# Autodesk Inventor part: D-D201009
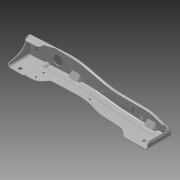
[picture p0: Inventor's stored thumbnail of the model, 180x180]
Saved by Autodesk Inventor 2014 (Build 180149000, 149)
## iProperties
Created: 2007-10
Part Number: D-D201009
Document SubType Name: Modeling
Designer: MM
Density: 7.85 g/cm^3
Mass: 1039.33 g
Surface Area: 1235.3 cm^2
Volume: 132.398 cm^3
Material: Steel
Description: TOP FRAME RIGHT SIDE PLATE
Appearance: Steel
Component Category: Lower Component
Author: MM
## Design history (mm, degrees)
sketch "Sketch2"
  geometry: L1 (-10, 0)-(-202.66, 0); L2 (-453.629, -13.843)-(-362.619, -13.843); L3 (-357.385, -13.706)-(-296.395, -10.51); L4 (-293.614, -10.266)-(-217.285, -0.894); L5 (-462.692, -8.069)-(-464.267, -4.692); L6 (-462.96, 10.251)-(-460.669, 13.523); L7 (-455.791, 17.222)-(-418.085, 30.463); L8 (-384.952, 36.111)-(-306.589, 36.111); L9 (-248.228, 43.019)-(-193.772, 56.092); L10 (-135.411, 63)-(-10, 63); L11 (0, 10)-(0, 53); A1 r 10 centre (-452.477, 7.787) between (-455.791, 17.222) and (-460.669, 13.523); A2 r 15 centre (-450.673, 1.647) between (-462.96, 10.251) and (-464.267, -4.692); A3 r 10 centre (-453.629, -3.843) between (-462.692, -8.069) and (-453.629, -13.843); A4 r 40 centre (-298.488, 29.435) between (-296.395, -10.51) and (-293.614, -10.266); A5 r 120 centre (-202.66, -120) between (-202.66, 0) and (-217.285, -0.894); A6 r 250 centre (-306.589, 286.111) between (-306.589, 36.111) and (-248.228, 43.019); A7 r 250 centre (-135.411, -187) between (-135.411, 63) and (-193.772, 56.092); A8 r 10 centre (-10, 53) between (0, 53) and (-10, 63); A9 r 10 centre (-10, 10) between (-10, 0) and (0, 10); A10 r 100 centre (-384.952, -63.889) between (-384.952, 36.111) and (-418.085, 30.463); A11 r 100 centre (-362.619, 86.157) between (-362.619, -13.843) and (-357.385, -13.706); 11 further points
  constraints: 22 end point, 22 point on circle, 22 point on line, 22 tangent, 11 centre point, 5 equal radius, 3 parallel, 1 horizontal, 1 perpendicular
  dimensions: "d0" = 210 distance of point (0, 0) point (-210, 0); "d1" = 85 horizontal distance of point (-210, 0) point (-295, -10.437); "d2" = 7 deg angle of L4 L1; "d3" = 65 horizontal distance of point (-360, -13.843) point (-295, -10.437); "d4" = 4 deg angle of L4 L3; "d5" = 460 horizontal distance of point (0, 0) point (-460, -13.843); "d6" = 65 deg angle of L5 L2; "d7" = 120 deg angle of L5 L6; "d8" = 17 vertical distance of point (-460, -13.843) point (-467.927, 3.157); "d9" = 30 vertical distance of point (-460, -13.843) point (-458.825, 16.157); "d10" = 63 distance of point (0, 0) point (0, 63); "d11" = 165 distance of point (-165, 63) point (0, 63); "d12" = 112 horizontal distance of point (-165, 63) point (-277, 36.111); "d13" = 13.5 deg angle of L10 L9; "d14" = 125 distance of point (-402, 36.111) point (-277, 36.111); "d15" = 10 radius of A1; "d16" = 15 radius of A2; "d17" = 40 radius of A4; "d18" = 120 radius of A5; "d19" = 250 radius of A6; "d26" = 100 radius of A10
extrude "Extrusion1" new body sketch "Sketch2" distance "d20" = 80; taper "d21" = 0 deg
sketch "Sketch3"
  geometry: L1 (0, 0)-(125.411, 0) reference; L2 (-10, 0)-(-10, -80) reference; L3 (125.411, 0)-(-10, -8.282); L4 (125.411, 0)-(-10, 0); L5 (-10, 0)-(-10, -8.282)
  constraints: 6 end point, 1 collinear, 1 perpendicular, 1 point on line
  dimensions: "d22" = 3.5 deg angle of L1 L3
extrude "Extrusion2" cut sketch "Sketch3" stored distance "d23" = 80; taper "d24" = 0 deg
fillet "Fillet1" dims "d25" = 500
sketch "Sketch4"
  geometry: L1 (202.66, 0)-(10, 0) reference; C1 r 8.5 at (60, -4.5); 1 further point
  constraints: 1 centre point
  dimensions: "d27" = 4.5 distance from line of C1.centre L1; "d28" = 60 horizontal distance of point (0, 0) C1.centre; "d29" = 17 diameter of C1
extrude "Extrusion3" cut sketch "Sketch4" stored distance "d30" = 80; taper "d31" = 0 deg
sketch "Sketch5"
  geometry: L1 (202.66, 0)-(67.211, 0) reference; L2 (293.614, -10.266)-(217.285, -0.894) reference; L3 (357.385, -13.706)-(296.395, -10.51) reference; L4 (453.629, -13.843)-(362.619, -13.843) reference; L5 (52.789, 0)-(10, 0) reference; L6 (60, -4.5)-(60, 4); L7 (202.66, 4)-(60, 4); L8 (461.629, -9.843)-(362.619, -9.843); L9 (357.594, -9.712)-(296.604, -6.515); L10 (294.101, -6.296)-(217.772, 3.076); A1 r 8.5 centre (60, -4.5) between (67.211, 0) and (52.789, 0) reference; A2 r 120 centre (202.66, -120) between (217.285, -0.894) and (202.66, 0) reference; A3 r 40 centre (298.488, 29.435) between (293.614, -10.266) and (296.395, -10.51) reference; A4 r 100 centre (362.619, 86.157) between (357.385, -13.706) and (362.619, -13.843) reference; A5 r 10 centre (453.629, -3.843) between (453.629, -13.843) and (462.692, -8.069) reference; A6 r 124 centre (202.66, -120) between (217.772, 3.076) and (202.66, 4); A7 r 96 centre (362.619, 86.157) between (357.594, -9.712) and (362.619, -9.843); A8 r 36 centre (298.488, 29.435) between (294.101, -6.296) and (296.604, -6.515); 1 further point
  constraints: 10 end point, 8 point on circle, 3 centre point, 2 parallel, 1 perpendicular, 1 tangent, 3 other
  dimensions: "d32" = 4 distance between parallel lines of L4 L8
extrude "Extrusion4" cut sketch "Sketch5" distance "d33" = 55; taper "d34" = 0 deg
fillet "Fillet4" dims "d38" = 10
fillet "Fillet5" dims "d39" = 10
fillet "Fillet6" dims "d40" = 3
fillet "Fillet7" dims "d41" = 3
workplane "Work Plane1"
sketch "Sketch10"
  geometry: L1 (-10, 58)-(-10, 80) reference; L2 (-10, 80)-(52.574, 80) reference; L3 (52.574, 80)-(52.574, 0) reference; L4 (52.574, 0)-(-6, 0) reference; L5 (-6, 0)-(-6, 52.343) reference; L6 (-10, 68)-(15.981, 83); L7 (15.981, 83)-(-10, 83); L8 (-10, 83)-(-10, 68); A1 r 3 centre (-9, 52.343) between (-6, 52.343) and (-8, 55.172) reference; A2 r 3 centre (-7, 58) between (-10, 58) and (-8, 55.172) reference; 1 further point
  constraints: 6 end point, 2 point on line, 1 collinear, 1 perpendicular
  dimensions: "d89" = 12 distance of L6.start point (-10, 80); "d90" = 60 deg angle of L1 L6; "d91" = 15 distance of L7.end L6.start
extrude "Extrusion9" cut sketch "Sketch10" stored distance "d92" = 40; taper "d93" = 0 deg
chamfer "Chamfer2" distance "d97" = 8; stored, may be unused: second distance "d98" = 20.48336, angle "d99" = 60 deg
chamfer "Chamfer3" distance "d100" = 8; stored, may be unused: second distance "d101" = 20.48336, angle "d102" = 60 deg
fillet "Fillet13" dims "d103" = 5
fillet "Fillet14" dims "d104" = 5
workplane "Work Plane2"
sketch "Sketch11"
  geometry: L1 (-23.843, 58)-(-23.843, 80) reference; L2 (-23.843, 80)-(24.973, 80) reference; L3 (24.973, 0)-(-19.843, 0) reference; L4 (-19.843, 0)-(-19.843, 52.343) reference; L5 (-23.843, 68)-(2.138, 83); L6 (2.138, 83)-(-23.843, 83); L7 (-23.843, 83)-(-23.843, 68); L8 (24.973, 80)-(24.973, 0) reference; A1 r 3 centre (-22.843, 52.343) between (-19.843, 52.343) and (-21.843, 55.172) reference; A2 r 3 centre (-20.843, 58) between (-23.843, 58) and (-21.843, 55.172) reference; 1 further point
  constraints: 6 end point, 1 collinear, 1 perpendicular, 1 point on line
  dimensions: "d106" = 12 distance of L5.start L1.end; "d107" = 60 deg angle of L5 L1; "d108" = 15 distance from line of L6 L5.start
extrude "Extrusion10" cut sketch "Sketch11" stored distance "d109" = 40; taper "d110" = 0 deg
chamfer "Chamfer4" distance "d111" = 8; stored, may be unused: second distance "d112" = 20.48336, angle "d113" = 60 deg
fillet "Fillet15" dims "d114" = 5
fillet "Fillet16" dims "d115" = 5
fillet "Fillet8" dims "d42" = 5
shell "Shell1" dims "d43" = 2.2
sketch "Sketch6"
  geometry: L1 (0, 0)-(43, 0) reference; L2 (43, 67.014)-(43, 0) reference; L3 (44.783, 61.182)-(35.908, 59.229); L4 (53, 67.32)-(53, 0) reference; L5 (52.306, 62)-(53, 62); L6 (16.726, 46.966)-(14.888, 44.549); L7 (6.448, 27.408)-(0.604, 5.902); L8 (-7.116, 0)-(-9, 0); L9 (-9, 0)-(-9, -7); L10 (-9, -7)-(53, -7); L11 (53, 62)-(53, -7); A1 r 33 centre (43, 27) between (35.908, 59.229) and (16.726, 46.966); A2 r 50 centre (54.698, 14.297) between (14.888, 44.549) and (6.448, 27.408); A3 r 35 centre (52.306, 27) between (52.306, 62) and (44.783, 61.182); A4 r 8 centre (-7.116, 8) between (-7.116, 0) and (0.604, 5.902); 4 further points
  constraints: 16 end point, 8 point on circle, 8 point on line, 8 tangent, 4 centre point, 3 perpendicular, 2 parallel, 1 collinear
  dimensions: "d44" = 62 distance from line of L4.end L5; "d45" = 66 diameter of A1; "d46" = 27 distance of A1.centre L1.end; "d47" = 4.5 distance of point (48.5, 62) L5.end; "d48" = 36.8 distance from line of L1 point (9, 36.8); "d49" = 54 distance from line of L4 point (-1, 0); "d50" = 62 distance between parallel lines of L11 L9; "d51" = 7 distance from line of L1.end L10; "d52" = 44 distance from line of L4 point (9, 36.8); "d53" = 50 radius of A2; "d54" = 35 radius of A3; "d55" = 8 radius of A4
extrude "Extrusion5" cut sketch "Sketch6" distance "d56" = 6; taper "d57" = 0 deg
sketch "Sketch7"
  geometry: L1 (0, 67.32)-(110.468, 74.077) reference; L2 (0, 67.32)-(0, 0) reference; L3 (0, 0)-(125.411, 0) reference; L4 (-4, 62)-(-4, 0) reference; L5 (-4, 62)-(-3.713, 62); L6 (2.283, 55.79)-(2.109, 50.802); L7 (10.592, 42.537)-(42.459, 44.486); L8 (49.966, 52.192)-(50.136, 57.07); L9 (54.134, 60.93)-(56.063, 60.93); L10 (57.435, 61.173)-(81.606, 70); L11 (43.814, 70)-(435, 70); L12 (237.061, 80)-(182.605, 80) reference; L13 (435, 70)-(435, 0); L14 (435, 0)-(-4, 0); L15 (-4, 0)-(-4, 62); A1 r 6 centre (-3.713, 56) between (2.283, 55.79) and (-3.713, 62); A2 r 8 centre (10.104, 50.522) between (2.109, 50.802) and (10.592, 42.537); A3 r 8 centre (41.971, 52.472) between (42.459, 44.486) and (49.966, 52.192); A4 r 4 centre (54.134, 56.93) between (54.134, 60.93) and (50.136, 57.07); A5 r 4 centre (56.063, 64.93) between (56.063, 60.93) and (57.435, 61.173); 8 further points
  constraints: 20 end point, 15 point on line, 10 point on circle, 10 tangent, 5 centre point, 4 parallel, 2 collinear, 2 equal radius, 2 perpendicular
  dimensions: "d58" = 10 distance between parallel lines of L11 L12; "d59" = 6.5 distance of L4.start point (2.5, 62); "d60" = 20 vertical distance of point (2.5, 62) point (1.802, 42); "d61" = 88 deg angle of L5 L6; "d62" = 48 distance of point (1.802, 42) point (49.712, 44.93); "d63" = 16 vertical distance of point (49.712, 44.93) point (50.271, 60.93); "d64" = 6.5 distance of point (50.271, 60.93) point (56.771, 60.93); "d65" = 31 distance from line of L10.end L8; "d66" = 435 distance between parallel lines of L2 L13; "d67" = 6 radius of A1; "d68" = 8 radius of A2; "d69" = 4 radius of A4
extrude "Extrusion6" cut sketch "Sketch7" distance "d72" = 45; taper "d73" = 0 deg
sketch "Sketch9"
  geometry: L1 (445, 21.011)-(445, 18.68) reference; L2 (445, 18.68)-(455.062, 15.146) reference; L3 (458.867, 12.261)-(461.158, 8.989) reference; L4 (445, 21.011)-(455.791, 17.222) reference; L5 (460.669, 13.523)-(458.867, 12.261); A1 r 7.8 centre (452.477, 7.787) between (458.867, 12.261) and (455.062, 15.146) reference; A2 r 10 centre (452.477, 7.787) between (460.669, 13.523) and (455.791, 17.222) reference; 1 further point
  constraints: 2 end point, 1 perpendicular
extrude "Extrusion7" cut sketch "Sketch9" distance "d75" = 73; taper "d76" = 0 deg
sketch "Sketch8"
  geometry: L1 (156.108, -22.121)-(101.652, -9.047) reference; L2 (293.346, -29.089)-(214.983, -29.089) reference; L3 (353.394, -44.32)-(325.749, -34.613) reference; L4 (43.804, -8.2)-(5, -8.2); L5 (351.406, -49.981)-(323.761, -40.274); L6 (293.346, -35.089)-(214.983, -35.089); L7 (154.707, -27.955)-(100.251, -14.881); L8 (353.394, -44.32)-(351.406, -49.981); L9 (43.804, -2.2)-(0, -2.2) reference; L10 (5, -8.2)-(5, -2.2); L11 (0, 0)-(0, -2.2) reference; A1 r 247.8 centre (43.804, -250) between (101.652, -9.047) and (43.804, -2.2) reference; A2 r 252.2 centre (214.983, 223.111) between (156.108, -22.121) and (214.983, -29.089) reference; A3 r 97.8 centre (293.346, -126.889) between (325.749, -34.613) and (293.346, -29.089) reference; A4 r 91.8 centre (293.346, -126.889) between (323.761, -40.274) and (293.346, -35.089); A5 r 258.2 centre (214.983, 223.111) between (154.707, -27.955) and (214.983, -35.089); A6 r 241.8 centre (43.804, -250) between (100.251, -14.881) and (43.804, -8.2); 1 further point
  constraints: 12 end point, 6 point on circle, 3 centre point, 2 perpendicular, 1 point on line, 4 other
  dimensions: "d77" = 6 distance between parallel lines of L3 L5; "d78" = 6 radial gap between concentric circles of A3 A4; "d81" = 5 distance between parallel lines of L11 L10; "d82" = 6 distance between parallel lines of L9 L4
extrude "Extrusion8" join sketch "Sketch8" distance "d79" = 2.2; taper "d80" = 0 deg
fillet "Fillet9" dims "d83" = 2.5
fillet "Fillet10" dims "d84" = 0.3
fillet "Fillet11" dims "d85" = 10
fillet "Fillet12" dims "d86" = 5
sketch "Sketch12"
  geometry: L1 (38.511, 67.32)-(38.511, 0) reference; L2 (0, 0)-(-28.281, 0); L3 (-47.011, 3.641)-(-48.511, 4.247); L4 (-63.601, 18.819)-(-63.95, 19.603); L5 (-74.494, 26.715)-(-168.594, 30.001); L6 (-205.015, 26.814)-(-216.579, 24.356); L7 (-247.766, 21.078)-(-298.348, 21.078); L8 (-328.989, 6.79)-(-349.791, -18); L9 (-349.791, -18)-(0, -18); L10 (0, -18)-(0, 0); L11 (-11.489, 0)-(-154.15, 0) reference; A1 r 10 centre (-186.122, 20.607) between (-185.773, 30.6) and (-188.201, 30.388); A2 r 50 centre (-28.281, 50) between (-47.011, 3.641) and (-28.281, 0); A3 r 28 centre (-38.022, 30.208) between (-63.601, 18.819) and (-48.511, 4.247); A4 r 12 centre (-74.913, 14.722) between (-63.95, 19.603) and (-74.494, 26.715); A5 r 150 centre (-173.828, -119.908) between (-168.594, 30.001) and (-205.015, 26.814); A6 r 150 centre (-247.766, 171.078) between (-247.766, 21.078) and (-216.579, 24.356); A7 r 40 centre (-298.348, -18.922) between (-298.348, 21.078) and (-328.989, 6.79); 7 further points
  constraints: 18 end point, 14 point on circle, 14 point on line, 14 tangent, 7 centre point, 2 parallel, 2 perpendicular, 1 equal radius
  dimensions: "d116" = 18 distance of L9.end L2.start; "d117" = 38 distance of L2.start point (-38, 0); "d118" = 21 horizontal distance of point (-59, 8.485) point (-38, 0); "d119" = 22 deg angle of L3 L2; "d120" = 8 horizontal distance of point (-59, 8.485) point (-67, 26.453); "d121" = 66 deg angle of L2 L4; "d122" = 120 horizontal distance of point (-187, 30.643) point (-67, 26.453); "d123" = 2 deg angle of L11 L5; "d124" = 45 horizontal distance of point (-232, 21.078) point (-187, 30.643); "d125" = 12 deg angle of L9 L6; "d126" = 85 distance of point (-232, 21.078) point (-317, 21.078); "d127" = 50 deg angle of L8 L7; "d128" = 10 radius of A1; "d129" = 50 radius of A2; "d130" = 28 radius of A3; "d131" = 12 radius of A4; "d132" = 150 radius of A5; "d133" = 40 radius of A7
extrude "Extrusion11" cut sketch "Sketch12" stored distance "d134" = 40; taper "d135" = 0 deg
fillet "Fillet17" dims "d136" = 20
fillet "Fillet18" dims "d137" = 10
sketch "Sketch13"
  geometry: L1 (384.952, -31.111)-(306.589, -31.111) reference; L2 (296.657, 5.517)-(357.647, 8.713) reference; L3 (217.894, -4.068)-(294.223, 5.304) reference; L4 (334.231, -21.656)-(311.461, -21.656); L5 (332.236, -2.132)-(297.659, -3.944); L6 (294.878, -4.187)-(266.95, -7.616); L7 (339.15, -15.762)-(337.417, -6.231); L8 (262.873, -10.836)-(260.164, -18.12); A1 r 255 centre (306.589, -286.111) between (306.589, -31.111) and (247.061, -38.157) reference; A2 r 264.5 centre (306.589, -286.111) between (311.461, -21.656) and (265.625, -24.803); A3 r 40 centre (299.753, -43.889) between (297.659, -3.944) and (294.878, -4.187); A4 r 5 centre (264.851, -19.863) between (260.164, -18.12) and (265.625, -24.803); A5 r 5 centre (267.56, -12.579) between (266.95, -7.616) and (262.873, -10.836); A6 r 5 centre (334.231, -16.656) between (334.231, -21.656) and (339.15, -15.762); A7 r 5 centre (332.498, -7.125) between (337.417, -6.231) and (332.236, -2.132); 7 further points
  constraints: 12 point on circle, 10 end point, 10 tangent, 6 centre point, 6 point on line, 3 equal radius, 1 parallel
  dimensions: "d138" = 9.5 distance between parallel lines of L2 L5; "d139" = 9.5 distance between parallel lines of L3 L6; "d140" = 9.5 radial gap between concentric circles of A1 A2; "d142" = 40 radius of A3; "d144" = 19.7546 vertical distance of point (340.222, -21.656) point (336.63, -1.901); "d145" = 72.69753 horizontal distance of point (263.933, -7.987) point (336.63, -1.901); "d147" = 62.5985 deg angle of L8 L6; "d148" = 5 radius of A4; "d149" = 97.3028 deg angle of L5 L7; "d193" = 42.04198 distance from line of L7 point (377.408, 8.843)
extrude "Extrusion12" cut sketch "Sketch13" distance "d150" = 2.2; taper "d151" = 0 deg
sketch "Sketch14"
  geometry: L1 (32.561, -15.349)-(30.828, -24.881) reference; L2 (25.647, -28.979)-(-8.93, -27.167) reference; L3 (-11.711, -26.924)-(-39.639, -23.495) reference; L4 (-43.716, -20.275)-(-46.425, -12.991) reference; L5 (4.872, -9.455)-(27.641, -9.455) reference; L6 (-48.487, -13.758)-(-45.778, -21.042); L7 (-39.907, -25.679)-(-11.979, -29.108); L8 (-9.045, -29.364)-(25.532, -31.176); L9 (32.993, -25.274)-(34.725, -15.743); L10 (27.641, -7.255)-(4.851, -7.255); A1 r 5 centre (27.641, -14.455) between (32.561, -15.349) and (27.641, -9.455) reference; A2 r 5 centre (25.909, -23.986) between (25.647, -28.979) and (30.828, -24.881) reference; A3 r 40 centre (-6.837, 12.778) between (-11.711, -26.924) and (-8.93, -27.167) reference; A4 r 5 centre (-39.03, -18.532) between (-43.716, -20.275) and (-39.639, -23.495) reference; A5 r 5 centre (-41.739, -11.248) between (-40.965, -6.309) and (-46.425, -12.991) reference; A6 r 264.5 centre (0, 255) between (-40.965, -6.309) and (4.872, -9.455) reference; A7 r 7.2 centre (-39.03, -18.532) between (-45.778, -21.042) and (-39.907, -25.679); A8 r 42.2 centre (-6.837, 12.778) between (-11.979, -29.108) and (-9.045, -29.364); A9 r 7.2 centre (25.909, -23.986) between (25.532, -31.176) and (32.993, -25.274); A10 r 7.2 centre (27.641, -14.455) between (34.725, -15.743) and (27.641, -7.255); A11 r 262.3 centre (0, 255) between (-40.624, -4.135) and (4.851, -7.255); A12 r 7.2 centre (-41.739, -11.248) between (-40.624, -4.135) and (-48.487, -13.758); 1 further point
  constraints: 12 point on circle, 10 end point, 6 centre point, 10 other
  dimensions: "d152" = 2.2 radial gap between concentric circles of A6 A11
extrude "Extrusion13" join sketch "Sketch14" distance "d153" = 2.2; taper "d154" = 0 deg
fillet "Fillet19" dims "d155" = 2.2
fillet "Fillet20" dims "d156" = 2.2
sketch "Sketch15"
  geometry: C1 r 5.25 at (20.905, 14.698); 1 further point
  constraints: 1 centre point
  dimensions: "d157" = 10.5 diameter of C1; "d158" = 65.302 vertical distance of C1.centre point (48.511, 80); "d159" = 27.606 horizontal distance of C1.centre point (48.511, 80)
extrude "Extrusion14" cut sketch "Sketch15" stored distance "d160" = 10; taper "d161" = 0 deg
sketch "Sketch16"
  geometry: C1 r 5.25 at (22.318, -30.122); A1 r 40 centre (106.771, -71.265) between (91.011, -34.5) and (76.329, -45.317) reference; 1 further point
  constraints: 1 centre point
  dimensions: "d162" = 10.5 diameter of C1; "d163" = 84.45243 horizontal distance of C1.centre A1.centre; "d164" = 41.14271 vertical distance of A1.centre C1.centre
extrude "Extrusion15" cut sketch "Sketch16" stored distance "d165" = 10; taper "d166" = 0 deg
fillet "Fillet21" dims "d167" = 2
fillet "Fillet22" dims "d168" = 2
fillet "Fillet23" dims "d169" = 2
workplane "Work Plane3"
  workaxis "Work Axis1"
sketch "Sketch17"
  geometry: A1 r 10 centre (450.673, -1.647) between (458.864, -7.383) and (459.736, 2.579) reference; 3 further points
  constraints: 1 coincident
  dimensions: "d186" = 365.52774 horizontal distance of point (365.528, -1.647) point (0, 0); "d187" = 1.64723 vertical distance of point (0, 0) point (365.528, -1.647)
hole "Hole1" sketch "Sketch17" at (450.673, -1.647), (365.528, -1.647) diameter "d179" = 14.65; stored, may be unused: countersink angle "d183" = 90 deg, drill point angle "d185" = 118 deg; dims "d180" = 6, "d181" = 4, "d182" = 2, "d184" = 8
hole "Hole2" diameter "d204" = 5.9; stored, may be unused: countersink angle "d208" = 90 deg, drill point angle "d210" = 118 deg; dims "d202" = 10, "d203" = 15, "d205" = 6, "d206" = 4, "d207" = 2, "d209" = 8
hole "Hole3" diameter "d213" = 5.9; stored, may be unused: countersink angle "d217" = 90 deg, drill point angle "d219" = 118 deg; dims "d211" = 15 (derived), "d212" = 120, "d214" = 6, "d215" = 4, "d216" = 2, "d218" = 8
hole "Hole4" diameter "d222" = 5.9; stored, may be unused: countersink angle "d226" = 90 deg, drill point angle "d228" = 118 deg; dims "d220" = 120 (derived), "d221" = 40, "d223" = 6, "d224" = 4, "d225" = 2, "d227" = 8
sketch "Sketch21"
  geometry: C1 r 15 at (87.294, 25.958)
  constraints: 1 centre point
  dimensions: "d232" = 30 diameter of C1
extrude "Extrusion17" cut sketch "Sketch21" stored distance "d233" = 10; taper "d234" = 0 deg
sketch "Sketch22"
  geometry: L1 (-124.405, 47.396)-(-123.092, 41.552) reference; L2 (-122.046, 33.112)-(-121.898, 31.274) reference; L3 (-121.15, 12.092)-(-121.054, 5) reference; L4 (-120.674, 5)-(-121.054, 5) reference; L5 (-120.674, 48)-(-120.674, 5) reference; L6 (-120.674, 48)-(-124.5, 48) reference; L7 (-98.674, 18.302)-(-98.674, 36.302); L8 (-92.674, 36.302)-(-92.674, 18.302); A1 r 3 centre (-95.674, 36.302) between (-92.674, 36.302) and (-98.674, 36.302); A2 r 3 centre (-95.674, 18.302) between (-98.674, 18.302) and (-92.674, 18.302); 3 further points; 3 other entities
  constraints: 4 end point, 4 point on circle, 4 tangent, 2 centre point, 2 parallel, 3 other
  dimensions: "d235" = 6 distance between parallel lines of L8 L7; "d236" = 18 distance of A1.centre A2.centre; "d237" = 25 distance from line of L5 A2.centre; "d238" = 25 vertical distance of point (-123.893, -6.698) A2.centre
extrude "Extrusion18" cut sketch "Sketch22" stored distance "d239" = 10; taper "d240" = 0 deg
sketch "Sketch23"
  geometry: L1 (-95.674, 18.302)-(-95.674, 36.302); A1 r 3 centre (-95.674, 36.302) between (-92.674, 36.302) and (-98.674, 36.302) reference; A2 r 3 centre (-95.674, 18.302) between (-98.674, 18.302) and (-92.674, 18.302) reference; 3 further points
  constraints: 2 coincident, 2 end point, 1 midpoint, 1 vertical
sketch "Sketch24"
  geometry: L1 (234.608, -31.107)-(234.608, -13.107); L2 (240.608, -13.107)-(240.608, -31.107); A1 r 3 centre (237.608, -13.107) between (240.608, -13.107) and (234.608, -13.107); A2 r 3 centre (237.608, -31.107) between (234.608, -31.107) and (240.608, -31.107)
  constraints: 4 end point, 4 point on circle, 4 tangent, 2 centre point, 1 parallel, 1 vertical
  dimensions: "d241" = 18 distance of A1.centre A2.centre; "d242" = 6 distance between parallel lines of L2 L1
extrude "Extrusion19" cut sketch "Sketch24" stored distance "d243" = 10; taper "d244" = 0 deg
sketch "Sketch25"
  geometry: L1 (237.608, -31.107)-(237.608, -13.107); A1 r 3 centre (237.608, -31.107) between (234.608, -31.107) and (240.608, -31.107) reference; A2 r 3 centre (237.608, -13.107) between (240.608, -13.107) and (234.608, -13.107) reference; 3 further points
  constraints: 2 coincident, 2 end point, 1 midpoint, 1 vertical
body "Solid1"
node "Projected Loop1"
node "Project Cut Edges1"
node "Project Cut Edges2"
other parameters: "d178" = 90 deg, "d229" = 0, "d230" = 0, "d231" = 0
